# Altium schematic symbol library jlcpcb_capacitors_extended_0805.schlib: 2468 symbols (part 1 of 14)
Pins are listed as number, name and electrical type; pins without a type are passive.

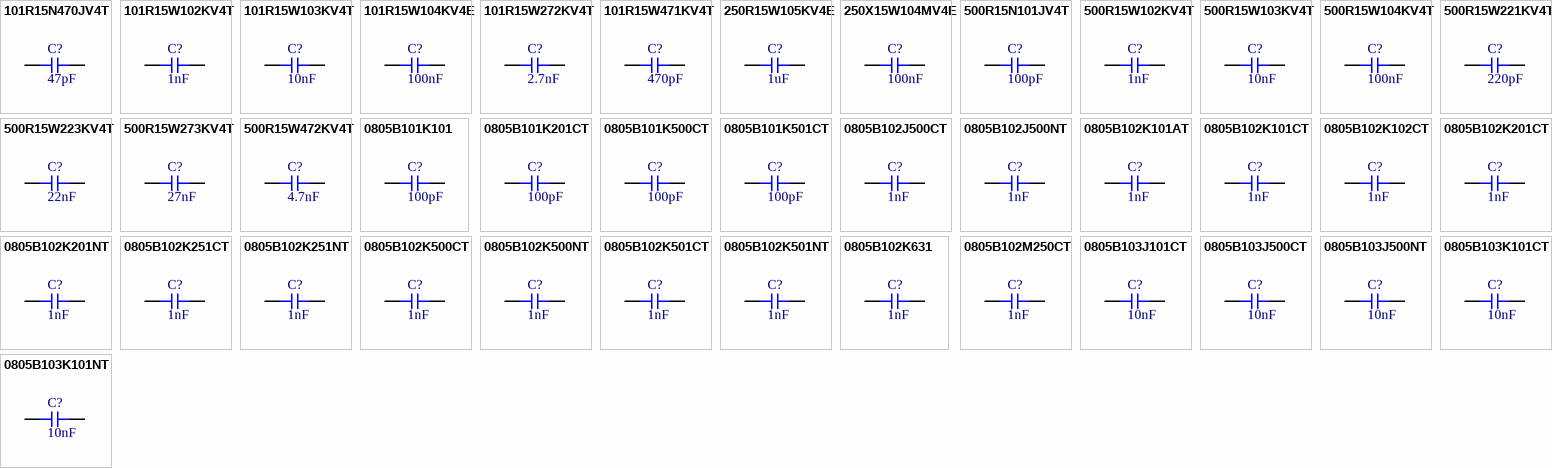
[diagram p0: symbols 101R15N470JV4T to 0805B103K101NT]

## 101R15N470JV4T
designator C?  Capacitance: 47pF  (hidden comment: *)
Capacitor, Ceramic (MLCC), 47pF, ±5%, 100V, NP0, ±5%, SMD 0805; Manufacturer: Johanson Dielectrics; Manufacturer Part Number: 101R15N470JV4T
footprint CAP-0805 (0805 (2012M) Capacitor)
pins: 1, 2

## 101R15W102KV4T
designator C?  Capacitance: 1nF  (hidden comment: *)
Capacitor, Ceramic (MLCC), 1nF, ±10%, 100V, X7R, ±10%, SMD 0805; Manufacturer: Johanson Dielectrics; Manufacturer Part Number: 101R15W102KV4T
footprint CAP-0805 (0805 (2012M) Capacitor)
pins: 1, 2

## 101R15W103KV4T
designator C?  Capacitance: 10nF  (hidden comment: *)
Capacitor, Ceramic (MLCC), 10nF, ±10%, 100V, X7R, ±10%, SMD 0805; Manufacturer: Johanson Dielectrics; Manufacturer Part Number: 101R15W103KV4T
footprint CAP-0805 (0805 (2012M) Capacitor)
pins: 1, 2

## 101R15W104KV4E
designator C?  Capacitance: 100nF  (hidden comment: *)
Capacitor, Ceramic (MLCC), 100nF, ±10%, 100V, X7R, ±10%, SMD 0805; Manufacturer: Johanson Dielectrics; Manufacturer Part Number: 101R15W104KV4E
footprint CAP-0805 (0805 (2012M) Capacitor)
pins: 1, 2

## 101R15W272KV4T
designator C?  Capacitance: 2.7nF  (hidden comment: *)
Capacitor, Ceramic (MLCC), 2.7nF, ±10%, 100V, X7R, ±10%, SMD 0805; Manufacturer: Johanson Dielectrics; Manufacturer Part Number: 101R15W272KV4T
footprint CAP-0805 (0805 (2012M) Capacitor)
pins: 1, 2

## 101R15W471KV4T
designator C?  Capacitance: 470pF  (hidden comment: *)
Capacitor, Ceramic (MLCC), 470pF, ±10%, 100V, X7R, ±10%, SMD 0805; Manufacturer: Johanson Dielectrics; Manufacturer Part Number: 101R15W471KV4T
footprint CAP-0805 (0805 (2012M) Capacitor)
pins: 1, 2

## 250R15W105KV4E
designator C?  Capacitance: 1uF  (hidden comment: *)
Capacitor, Ceramic (MLCC), 1uF, ±10%, 25V, X7R, ±10%, SMD 0805; Manufacturer: Johanson Dielectrics; Manufacturer Part Number: 250R15W105KV4E
footprint CAP-0805 (0805 (2012M) Capacitor)
pins: 1, 2

## 250X15W104MV4E
designator C?  Capacitance: 100nF  (hidden comment: *)
Capacitor, Ceramic (MLCC), 100nF, ±20%, 25V, X7R, ±20%, SMD 0805; Manufacturer: Johanson Dielectrics; Manufacturer Part Number: 250X15W104MV4E
footprint CAP-0805 (0805 (2012M) Capacitor)
pins: 1, 2

## 500R15N101JV4T
designator C?  Capacitance: 100pF  (hidden comment: *)
Capacitor, Ceramic (MLCC), 100pF, ±5%, 50V, NP0, ±5%, SMD 0805; Manufacturer: Johanson Dielectrics; Manufacturer Part Number: 500R15N101JV4T
footprint CAP-0805 (0805 (2012M) Capacitor)
pins: 1, 2

## 500R15W102KV4T
designator C?  Capacitance: 1nF  (hidden comment: *)
Capacitor, Ceramic (MLCC), 1nF, ±10%, 50V, X7R, ±10%, SMD 0805; Manufacturer: Johanson Dielectrics; Manufacturer Part Number: 500R15W102KV4T
footprint CAP-0805 (0805 (2012M) Capacitor)
pins: 1, 2

## 500R15W103KV4T
designator C?  Capacitance: 10nF  (hidden comment: *)
Capacitor, Ceramic (MLCC), 10nF, ±10%, 50V, X7R, ±10%, SMD 0805; Manufacturer: Johanson Dielectrics; Manufacturer Part Number: 500R15W103KV4T
footprint CAP-0805 (0805 (2012M) Capacitor)
pins: 1, 2

## 500R15W104KV4T
designator C?  Capacitance: 100nF  (hidden comment: *)
Capacitor, Ceramic (MLCC), 100nF, ±10%, 50V, X7R, ±10%, SMD 0805; Manufacturer: Johanson Dielectrics; Manufacturer Part Number: 500R15W104KV4T
footprint CAP-0805 (0805 (2012M) Capacitor)
pins: 1, 2

## 500R15W221KV4T
designator C?  Capacitance: 220pF  (hidden comment: *)
Capacitor, Ceramic (MLCC), 220pF, ±10%, 50V, X7R, ±10%, SMD 0805; Manufacturer: Johanson Dielectrics; Manufacturer Part Number: 500R15W221KV4T
footprint CAP-0805 (0805 (2012M) Capacitor)
pins: 1, 2

## 500R15W223KV4T
designator C?  Capacitance: 22nF  (hidden comment: *)
Capacitor, Ceramic (MLCC), 22nF, ±10%, 50V, X7R, ±10%, SMD 0805; Manufacturer: Johanson Dielectrics; Manufacturer Part Number: 500R15W223KV4T
footprint CAP-0805 (0805 (2012M) Capacitor)
pins: 1, 2

## 500R15W273KV4T
designator C?  Capacitance: 27nF  (hidden comment: *)
Capacitor, Ceramic (MLCC), 27nF, ±10%, 50V, X7R, ±10%, SMD 0805; Manufacturer: Johanson Dielectrics; Manufacturer Part Number: 500R15W273KV4T
footprint CAP-0805 (0805 (2012M) Capacitor)
pins: 1, 2

## 500R15W472KV4T
designator C?  Capacitance: 4.7nF  (hidden comment: *)
Capacitor, Ceramic (MLCC), 4.7nF, ±10%, 50V, X7R, ±10%, SMD 0805; Manufacturer: Johanson Dielectrics; Manufacturer Part Number: 500R15W472KV4T
footprint CAP-0805 (0805 (2012M) Capacitor)
pins: 1, 2

## 0805B101K101
designator C?  Capacitance: 100pF  (hidden comment: *)
Capacitor, Ceramic (MLCC), 100pF, ±10%, 100V, X7R, ±10%, SMD 0805; Manufacturer: Walsin Tech Corp; Manufacturer Part Number: 0805B101K101
footprint CAP-0805 (0805 (2012M) Capacitor)
pins: 1, 2

## 0805B101K201CT
designator C?  Capacitance: 100pF  (hidden comment: *)
Capacitor, Ceramic (MLCC), 100pF, ±10%, 200V, X7R, ±10%, SMD 0805; Manufacturer: Walsin Tech Corp; Manufacturer Part Number: 0805B101K201CT
footprint CAP-0805 (0805 (2012M) Capacitor)
pins: 1, 2

## 0805B101K500CT
designator C?  Capacitance: 100pF  (hidden comment: *)
Capacitor, Ceramic (MLCC), 100pF, ±10%, 50V, X7R, ±10%, SMD 0805; Manufacturer: Walsin Tech Corp; Manufacturer Part Number: 0805B101K500CT
footprint CAP-0805 (0805 (2012M) Capacitor)
pins: 1, 2

## 0805B101K501CT
designator C?  Capacitance: 100pF  (hidden comment: *)
Capacitor, Ceramic (MLCC), 100pF, ±10%, 500V, X7R, ±10%, SMD 0805; Manufacturer: Walsin Tech Corp; Manufacturer Part Number: 0805B101K501CT
footprint CAP-0805 (0805 (2012M) Capacitor)
pins: 1, 2

## 0805B102J500CT
designator C?  Capacitance: 1nF  (hidden comment: *)
Capacitor, Ceramic (MLCC), 1nF, ±5%, 50V, X7R, ±5%, SMD 0805; Manufacturer: Walsin Tech Corp; Manufacturer Part Number: 0805B102J500CT
footprint CAP-0805 (0805 (2012M) Capacitor)
pins: 1, 2

## 0805B102J500NT
designator C?  Capacitance: 1nF  (hidden comment: *)
Capacitor, Ceramic (MLCC), 1nF, ±5%, 50V, X7R, ±5%, SMD 0805; Manufacturer: FH(Guangdong Fenghua Advanced Tech); Manufacturer Part Number: 0805B102J500NT
footprint CAP-0805 (0805 (2012M) Capacitor)
pins: 1, 2

## 0805B102K101AT
designator C?  Capacitance: 1nF  (hidden comment: *)
Capacitor, Ceramic (MLCC), 1nF, ±10%, 100V, X7R, ±10%, SMD 0805; Manufacturer: FH(Guangdong Fenghua Advanced Tech); Manufacturer Part Number: 0805B102K101AT
footprint CAP-0805 (0805 (2012M) Capacitor)
pins: 1, 2

## 0805B102K101CT
designator C?  Capacitance: 1nF  (hidden comment: *)
Capacitor, Ceramic (MLCC), 1nF, ±10%, 100V, X7R, ±10%, SMD 0805; Manufacturer: Walsin Tech Corp; Manufacturer Part Number: 0805B102K101CT
footprint CAP-0805 (0805 (2012M) Capacitor)
pins: 1, 2

## 0805B102K102CT
designator C?  Capacitance: 1nF  (hidden comment: *)
Capacitor, Ceramic (MLCC), 1nF, ±10%, 1kV, X7R, ±10%, SMD 0805; Manufacturer: Walsin Tech Corp; Manufacturer Part Number: 0805B102K102CT
footprint CAP-0805 (0805 (2012M) Capacitor)
pins: 1, 2

## 0805B102K201CT
designator C?  Capacitance: 1nF  (hidden comment: *)
Capacitor, Ceramic (MLCC), 1nF, ±10%, 200V, X7R, ±10%, SMD 0805; Manufacturer: Walsin Tech Corp; Manufacturer Part Number: 0805B102K201CT
footprint CAP-0805 (0805 (2012M) Capacitor)
pins: 1, 2

## 0805B102K201NT
designator C?  Capacitance: 1nF  (hidden comment: *)
Capacitor, Ceramic (MLCC), 1nF, ±10%, 200V, X7R, ±10%, SMD 0805; Manufacturer: FH(Guangdong Fenghua Advanced Tech); Manufacturer Part Number: 0805B102K201NT
footprint CAP-0805 (0805 (2012M) Capacitor)
pins: 1, 2

## 0805B102K251CT
designator C?  Capacitance: 1nF  (hidden comment: *)
Capacitor, Ceramic (MLCC), 1nF, ±10%, 250V, X7R, ±10%, SMD 0805; Manufacturer: Walsin Tech Corp; Manufacturer Part Number: 0805B102K251CT
footprint CAP-0805 (0805 (2012M) Capacitor)
pins: 1, 2

## 0805B102K251NT
designator C?  Capacitance: 1nF  (hidden comment: *)
Capacitor, Ceramic (MLCC), 1nF, ±10%, 250V, X7R, ±10%, SMD 0805; Manufacturer: FH(Guangdong Fenghua Advanced Tech); Manufacturer Part Number: 0805B102K251NT
footprint CAP-0805 (0805 (2012M) Capacitor)
pins: 1, 2

## 0805B102K500CT
designator C?  Capacitance: 1nF  (hidden comment: *)
Capacitor, Ceramic (MLCC), 1nF, ±10%, 50V, X7R, ±10%, SMD 0805; Manufacturer: Walsin Tech Corp; Manufacturer Part Number: 0805B102K500CT
footprint CAP-0805 (0805 (2012M) Capacitor)
pins: 1, 2

## 0805B102K500NT
designator C?  Capacitance: 1nF  (hidden comment: *)
Capacitor, Ceramic (MLCC), 1nF, ±10%, 50V, X7R, ±10%, SMD 0805; Manufacturer: FH(Guangdong Fenghua Advanced Tech); Manufacturer Part Number: 0805B102K500NT
footprint CAP-0805 (0805 (2012M) Capacitor)
pins: 1, 2

## 0805B102K501CT
designator C?  Capacitance: 1nF  (hidden comment: *)
Capacitor, Ceramic (MLCC), 1nF, ±10%, 500V, X7R, ±10%, SMD 0805; Manufacturer: Walsin Tech Corp; Manufacturer Part Number: 0805B102K501CT
footprint CAP-0805 (0805 (2012M) Capacitor)
pins: 1, 2

## 0805B102K501NT
designator C?  Capacitance: 1nF  (hidden comment: *)
Capacitor, Ceramic (MLCC), 1nF, ±10%, 500V, ±10%, SMD 0805; Manufacturer: FH(Guangdong Fenghua Advanced Tech); Manufacturer Part Number: 0805B102K501NT
footprint CAP-0805 (0805 (2012M) Capacitor)
pins: 1, 2

## 0805B102K631
designator C?  Capacitance: 1nF  (hidden comment: *)
Capacitor, Ceramic (MLCC), 1nF, ±10%, 630V, X7R, ±10%, SMD 0805; Manufacturer: Walsin Tech Corp; Manufacturer Part Number: 0805B102K631
footprint CAP-0805 (0805 (2012M) Capacitor)
pins: 1, 2

## 0805B102M250CT
designator C?  Capacitance: 1nF  (hidden comment: *)
Capacitor, Ceramic (MLCC), 1nF, ±20%, 25V, X7R, ±20%, SMD 0805; Manufacturer: Walsin Tech Corp; Manufacturer Part Number: 0805B102M250CT
footprint CAP-0805 (0805 (2012M) Capacitor)
pins: 1, 2

## 0805B103J101CT
designator C?  Capacitance: 10nF  (hidden comment: *)
Capacitor, Ceramic (MLCC), 10nF, ±5%, 100V, X7R, ±5%, SMD 0805; Manufacturer: Walsin Tech Corp; Manufacturer Part Number: 0805B103J101CT
footprint CAP-0805 (0805 (2012M) Capacitor)
pins: 1, 2

## 0805B103J500CT
designator C?  Capacitance: 10nF  (hidden comment: *)
Capacitor, Ceramic (MLCC), 10nF, ±5%, 50V, X7R, ±5%, SMD 0805; Manufacturer: Walsin Tech Corp; Manufacturer Part Number: 0805B103J500CT
footprint CAP-0805 (0805 (2012M) Capacitor)
pins: 1, 2

## 0805B103J500NT
designator C?  Capacitance: 10nF  (hidden comment: *)
Capacitor, Ceramic (MLCC), 10nF, ±5%, 50V, X7R, ±5%, SMD 0805; Manufacturer: FH(Guangdong Fenghua Advanced Tech); Manufacturer Part Number: 0805B103J500NT
footprint CAP-0805 (0805 (2012M) Capacitor)
pins: 1, 2

## 0805B103K101CT
designator C?  Capacitance: 10nF  (hidden comment: *)
Capacitor, Ceramic (MLCC), 10nF, ±10%, 100V, X7R, ±10%, SMD 0805; Manufacturer: Walsin Tech Corp; Manufacturer Part Number: 0805B103K101CT
footprint CAP-0805 (0805 (2012M) Capacitor)
pins: 1, 2

## 0805B103K101NT
designator C?  Capacitance: 10nF  (hidden comment: *)
Capacitor, Ceramic (MLCC), 10nF, ±10%, 100V, X7R, ±10%, SMD 0805; Manufacturer: FH(Guangdong Fenghua Advanced Tech); Manufacturer Part Number: 0805B103K101NT
footprint CAP-0805 (0805 (2012M) Capacitor)
pins: 1, 2

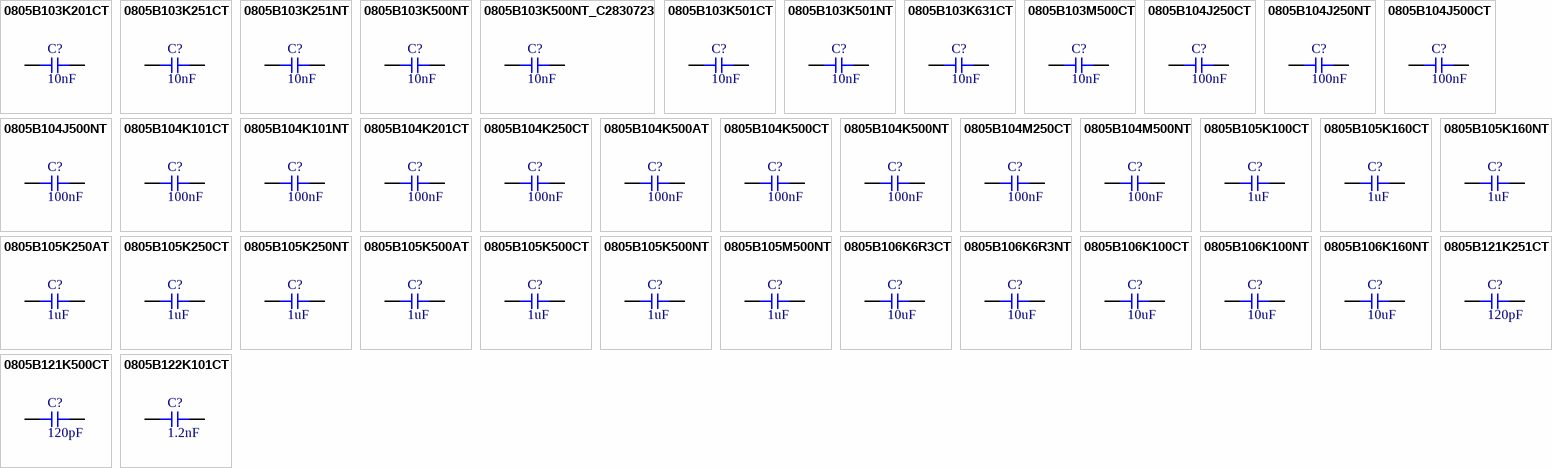
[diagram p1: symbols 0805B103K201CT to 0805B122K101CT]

## 0805B103K201CT
designator C?  Capacitance: 10nF  (hidden comment: *)
Capacitor, Ceramic (MLCC), 10nF, ±10%, 200V, X7R, ±10%, SMD 0805; Manufacturer: Walsin Tech Corp; Manufacturer Part Number: 0805B103K201CT
footprint CAP-0805 (0805 (2012M) Capacitor)
pins: 1, 2

## 0805B103K251CT
designator C?  Capacitance: 10nF  (hidden comment: *)
Capacitor, Ceramic (MLCC), 10nF, ±10%, 250V, X7R, ±10%, SMD 0805; Manufacturer: Walsin Tech Corp; Manufacturer Part Number: 0805B103K251CT
footprint CAP-0805 (0805 (2012M) Capacitor)
pins: 1, 2

## 0805B103K251NT
designator C?  Capacitance: 10nF  (hidden comment: *)
Capacitor, Ceramic (MLCC), 10nF, ±10%, 250V, X7R, ±10%, SMD 0805; Manufacturer: FH(Guangdong Fenghua Advanced Tech); Manufacturer Part Number: 0805B103K251NT
footprint CAP-0805 (0805 (2012M) Capacitor)
pins: 1, 2

## 0805B103K500NT
designator C?  Capacitance: 10nF  (hidden comment: *)
Capacitor, Ceramic (MLCC), 10nF, ±10%, 50V, X7R, ±10%, SMD 0805; Manufacturer: FH(Guangdong Fenghua Advanced Tech); Manufacturer Part Number: 0805B103K500NT
footprint CAP-0805 (0805 (2012M) Capacitor)
pins: 1, 2

## 0805B103K500NT_C2830723
designator C?  Capacitance: 10nF  (hidden comment: *)
Capacitor, Ceramic (MLCC), 10nF, ±10%, 50V, ±10%, SMD 0805; Manufacturer: FH-BK(Guangdong Fenghua Bangke Elec); Manufacturer Part Number: 0805B103K500NT
footprint CAP-0805 (0805 (2012M) Capacitor)
pins: 1, 2

## 0805B103K501CT
designator C?  Capacitance: 10nF  (hidden comment: *)
Capacitor, Ceramic (MLCC), 10nF, ±10%, 500V, X7R, ±10%, SMD 0805; Manufacturer: Walsin Tech Corp; Manufacturer Part Number: 0805B103K501CT
footprint CAP-0805 (0805 (2012M) Capacitor)
pins: 1, 2

## 0805B103K501NT
designator C?  Capacitance: 10nF  (hidden comment: *)
Capacitor, Ceramic (MLCC), 10nF, ±10%, 500V, ±10%, SMD 0805; Manufacturer: FH(Guangdong Fenghua Advanced Tech); Manufacturer Part Number: 0805B103K501NT
footprint CAP-0805 (0805 (2012M) Capacitor)
pins: 1, 2

## 0805B103K631CT
designator C?  Capacitance: 10nF  (hidden comment: *)
Capacitor, Ceramic (MLCC), 10nF, ±10%, 630V, X7R, ±10%, SMD 0805; Manufacturer: Walsin Tech Corp; Manufacturer Part Number: 0805B103K631CT
footprint CAP-0805 (0805 (2012M) Capacitor)
pins: 1, 2

## 0805B103M500CT
designator C?  Capacitance: 10nF  (hidden comment: *)
Capacitor, Ceramic (MLCC), 10nF, ±20%, 50V, X7R, ±20%, SMD 0805; Manufacturer: Walsin Tech Corp; Manufacturer Part Number: 0805B103M500CT
footprint CAP-0805 (0805 (2012M) Capacitor)
pins: 1, 2

## 0805B104J250CT
designator C?  Capacitance: 100nF  (hidden comment: *)
Capacitor, Ceramic (MLCC), 100nF, ±5%, 25V, X7R, ±5%, SMD 0805; Manufacturer: Walsin Tech Corp; Manufacturer Part Number: 0805B104J250CT
footprint CAP-0805 (0805 (2012M) Capacitor)
pins: 1, 2

## 0805B104J250NT
designator C?  Capacitance: 100nF  (hidden comment: *)
Capacitor, Ceramic (MLCC), 100nF, ±5%, 25V, X7R, ±5%, SMD 0805; Manufacturer: FH(Guangdong Fenghua Advanced Tech); Manufacturer Part Number: 0805B104J250NT
footprint CAP-0805 (0805 (2012M) Capacitor)
pins: 1, 2

## 0805B104J500CT
designator C?  Capacitance: 100nF  (hidden comment: *)
Capacitor, Ceramic (MLCC), 100nF, ±5%, 50V, X7R, ±5%, SMD 0805; Manufacturer: Walsin Tech Corp; Manufacturer Part Number: 0805B104J500CT
footprint CAP-0805 (0805 (2012M) Capacitor)
pins: 1, 2

## 0805B104J500NT
designator C?  Capacitance: 100nF  (hidden comment: *)
Capacitor, Ceramic (MLCC), 100nF, ±5%, 50V, X7R, ±5%, SMD 0805; Manufacturer: FH(Guangdong Fenghua Advanced Tech); Manufacturer Part Number: 0805B104J500NT
footprint CAP-0805 (0805 (2012M) Capacitor)
pins: 1, 2

## 0805B104K101CT
designator C?  Capacitance: 100nF  (hidden comment: *)
Capacitor, Ceramic (MLCC), 100nF, ±10%, 100V, X7R, ±10%, SMD 0805; Manufacturer: Walsin Tech Corp; Manufacturer Part Number: 0805B104K101CT
footprint CAP-0805 (0805 (2012M) Capacitor)
pins: 1, 2

## 0805B104K101NT
designator C?  Capacitance: 100nF  (hidden comment: *)
Capacitor, Ceramic (MLCC), 100nF, ±10%, 100V, X7R, ±10%, SMD 0805; Manufacturer: FH(Guangdong Fenghua Advanced Tech); Manufacturer Part Number: 0805B104K101NT
footprint CAP-0805 (0805 (2012M) Capacitor)
pins: 1, 2

## 0805B104K201CT
designator C?  Capacitance: 100nF  (hidden comment: *)
Capacitor, Ceramic (MLCC), 100nF, ±10%, 200V, X7R, ±10%, SMD 0805; Manufacturer: Walsin Tech Corp; Manufacturer Part Number: 0805B104K201CT
footprint CAP-0805 (0805 (2012M) Capacitor)
pins: 1, 2

## 0805B104K250CT
designator C?  Capacitance: 100nF  (hidden comment: *)
Capacitor, Ceramic (MLCC), 100nF, ±10%, 25V, X7R, ±10%, SMD 0805; Manufacturer: Walsin Tech Corp; Manufacturer Part Number: 0805B104K250CT
footprint CAP-0805 (0805 (2012M) Capacitor)
pins: 1, 2

## 0805B104K500AT
designator C?  Capacitance: 100nF  (hidden comment: *)
Capacitor, Ceramic (MLCC), 100nF, ±10%, 50V, ±10%, SMD 0805; Manufacturer: FH(Guangdong Fenghua Advanced Tech); Manufacturer Part Number: 0805B104K500AT
footprint CAP-0805 (0805 (2012M) Capacitor)
pins: 1, 2

## 0805B104K500CT
designator C?  Capacitance: 100nF  (hidden comment: *)
Capacitor, Ceramic (MLCC), 100nF, ±10%, 50V, X7R, ±10%, SMD 0805; Manufacturer: Walsin Tech Corp; Manufacturer Part Number: 0805B104K500CT
footprint CAP-0805 (0805 (2012M) Capacitor)
pins: 1, 2

## 0805B104K500NT
designator C?  Capacitance: 100nF  (hidden comment: *)
Capacitor, Ceramic (MLCC), 100nF, ±10%, 50V, X7R, ±10%, SMD 0805; Manufacturer: FH(Guangdong Fenghua Advanced Tech); Manufacturer Part Number: 0805B104K500NT
footprint CAP-0805 (0805 (2012M) Capacitor)
pins: 1, 2

## 0805B104M250CT
designator C?  Capacitance: 100nF  (hidden comment: *)
Capacitor, Ceramic (MLCC), 100nF, ±20%, 25V, X7R, ±20%, SMD 0805; Manufacturer: Walsin Tech Corp; Manufacturer Part Number: 0805B104M250CT
footprint CAP-0805 (0805 (2012M) Capacitor)
pins: 1, 2

## 0805B104M500NT
designator C?  Capacitance: 100nF  (hidden comment: *)
Capacitor, Ceramic (MLCC), 100nF, ±20%, 50V, X7R, ±20%, SMD 0805; Manufacturer: FH(Guangdong Fenghua Advanced Tech); Manufacturer Part Number: 0805B104M500NT
footprint CAP-0805 (0805 (2012M) Capacitor)
pins: 1, 2

## 0805B105K100CT
designator C?  Capacitance: 1uF  (hidden comment: *)
Capacitor, Ceramic (MLCC), 1uF, ±10%, 10V, X7R, ±10%, SMD 0805; Manufacturer: Walsin Tech Corp; Manufacturer Part Number: 0805B105K100CT
footprint CAP-0805 (0805 (2012M) Capacitor)
pins: 1, 2

## 0805B105K160CT
designator C?  Capacitance: 1uF  (hidden comment: *)
Capacitor, Ceramic (MLCC), 1uF, ±10%, 16V, X7R, ±10%, SMD 0805; Manufacturer: Walsin Tech Corp; Manufacturer Part Number: 0805B105K160CT
footprint CAP-0805 (0805 (2012M) Capacitor)
pins: 1, 2

## 0805B105K160NT
designator C?  Capacitance: 1uF  (hidden comment: *)
Capacitor, Ceramic (MLCC), 1uF, ±10%, 16V, X7R, ±10%, SMD 0805; Manufacturer: FH(Guangdong Fenghua Advanced Tech); Manufacturer Part Number: 0805B105K160NT
footprint CAP-0805 (0805 (2012M) Capacitor)
pins: 1, 2

## 0805B105K250AT
designator C?  Capacitance: 1uF  (hidden comment: *)
Capacitor, Ceramic (MLCC), 1uF, ±10%, 25V, X7R, ±10%, SMD 0805; Manufacturer: FH(Guangdong Fenghua Advanced Tech); Manufacturer Part Number: 0805B105K250AT
footprint CAP-0805 (0805 (2012M) Capacitor)
pins: 1, 2

## 0805B105K250CT
designator C?  Capacitance: 1uF  (hidden comment: *)
Capacitor, Ceramic (MLCC), 1uF, ±10%, 25V, X7R, ±10%, SMD 0805; Manufacturer: Walsin Tech Corp; Manufacturer Part Number: 0805B105K250CT
footprint CAP-0805 (0805 (2012M) Capacitor)
pins: 1, 2

## 0805B105K250NT
designator C?  Capacitance: 1uF  (hidden comment: *)
Capacitor, Ceramic (MLCC), 1uF, ±10%, 25V, X7R, ±10%, SMD 0805; Manufacturer: FH(Guangdong Fenghua Advanced Tech); Manufacturer Part Number: 0805B105K250NT
footprint CAP-0805 (0805 (2012M) Capacitor)
pins: 1, 2

## 0805B105K500AT
designator C?  Capacitance: 1uF  (hidden comment: *)
Capacitor, Ceramic (MLCC), 1uF, ±10%, 50V, X7R, ±10%, SMD 0805; Manufacturer: FH(Guangdong Fenghua Advanced Tech); Manufacturer Part Number: 0805B105K500AT
footprint CAP-0805 (0805 (2012M) Capacitor)
pins: 1, 2

## 0805B105K500CT
designator C?  Capacitance: 1uF  (hidden comment: *)
Capacitor, Ceramic (MLCC), 1uF, ±10%, 50V, X7R, ±10%, SMD 0805; Manufacturer: Walsin Tech Corp; Manufacturer Part Number: 0805B105K500CT
footprint CAP-0805 (0805 (2012M) Capacitor)
pins: 1, 2

## 0805B105K500NT
designator C?  Capacitance: 1uF  (hidden comment: *)
Capacitor, Ceramic (MLCC), 1uF, ±10%, 50V, X7R, ±10%, SMD 0805; Manufacturer: FH(Guangdong Fenghua Advanced Tech); Manufacturer Part Number: 0805B105K500NT
footprint CAP-0805 (0805 (2012M) Capacitor)
pins: 1, 2

## 0805B105M500NT
designator C?  Capacitance: 1uF  (hidden comment: *)
Capacitor, Ceramic (MLCC), 1uF, ±20%, 50V, X7R, ±20%, SMD 0805; Manufacturer: FH (Guangdong Fenghua Advanced Tech); Manufacturer Part Number: 0805B105M500NT
footprint CAP-0805 (0805 (2012M) Capacitor)
pins: 1, 2

## 0805B106K6R3CT
designator C?  Capacitance: 10uF  (hidden comment: *)
Capacitor, Ceramic (MLCC), 10uF, ±10%, 6.3V, X7R, ±10%, SMD 0805; Manufacturer: Walsin Tech Corp; Manufacturer Part Number: 0805B106K6R3CT
footprint CAP-0805 (0805 (2012M) Capacitor)
pins: 1, 2

## 0805B106K6R3NT
designator C?  Capacitance: 10uF  (hidden comment: *)
Capacitor, Ceramic (MLCC), 10uF, ±10%, 6.3V, X7R, ±10%, SMD 0805; Manufacturer: FH(Guangdong Fenghua Advanced Tech); Manufacturer Part Number: 0805B106K6R3NT
footprint CAP-0805 (0805 (2012M) Capacitor)
pins: 1, 2

## 0805B106K100CT
designator C?  Capacitance: 10uF  (hidden comment: *)
Capacitor, Ceramic (MLCC), 10uF, ±10%, 10V, X7R, ±10%, SMD 0805; Manufacturer: Walsin Tech Corp; Manufacturer Part Number: 0805B106K100CT
footprint CAP-0805 (0805 (2012M) Capacitor)
pins: 1, 2

## 0805B106K100NT
designator C?  Capacitance: 10uF  (hidden comment: *)
Capacitor, Ceramic (MLCC), 10uF, ±10%, 10V, X7R, ±10%, SMD 0805; Manufacturer: FH(Guangdong Fenghua Advanced Tech); Manufacturer Part Number: 0805B106K100NT
footprint CAP-0805 (0805 (2012M) Capacitor)
pins: 1, 2

## 0805B106K160NT
designator C?  Capacitance: 10uF  (hidden comment: *)
Capacitor, Ceramic (MLCC), 10uF, ±10%, 16V, X7R, ±10%, SMD 0805; Manufacturer: FH(Guangdong Fenghua Advanced Tech); Manufacturer Part Number: 0805B106K160NT
footprint CAP-0805 (0805 (2012M) Capacitor)
pins: 1, 2

## 0805B121K251CT
designator C?  Capacitance: 120pF  (hidden comment: *)
Capacitor, Ceramic (MLCC), 120pF, ±10%, 250V, X7R, ±10%, SMD 0805; Manufacturer: Walsin Tech Corp; Manufacturer Part Number: 0805B121K251CT
footprint CAP-0805 (0805 (2012M) Capacitor)
pins: 1, 2

## 0805B121K500CT
designator C?  Capacitance: 120pF  (hidden comment: *)
Capacitor, Ceramic (MLCC), 120pF, ±10%, 50V, X7R, ±10%, SMD 0805; Manufacturer: Walsin Tech Corp; Manufacturer Part Number: 0805B121K500CT
footprint CAP-0805 (0805 (2012M) Capacitor)
pins: 1, 2

## 0805B122K101CT
designator C?  Capacitance: 1.2nF  (hidden comment: *)
Capacitor, Ceramic (MLCC), 1.2nF, ±10%, 100V, X7R, ±10%, SMD 0805; Manufacturer: Walsin Tech Corp; Manufacturer Part Number: 0805B122K101CT
footprint CAP-0805 (0805 (2012M) Capacitor)
pins: 1, 2

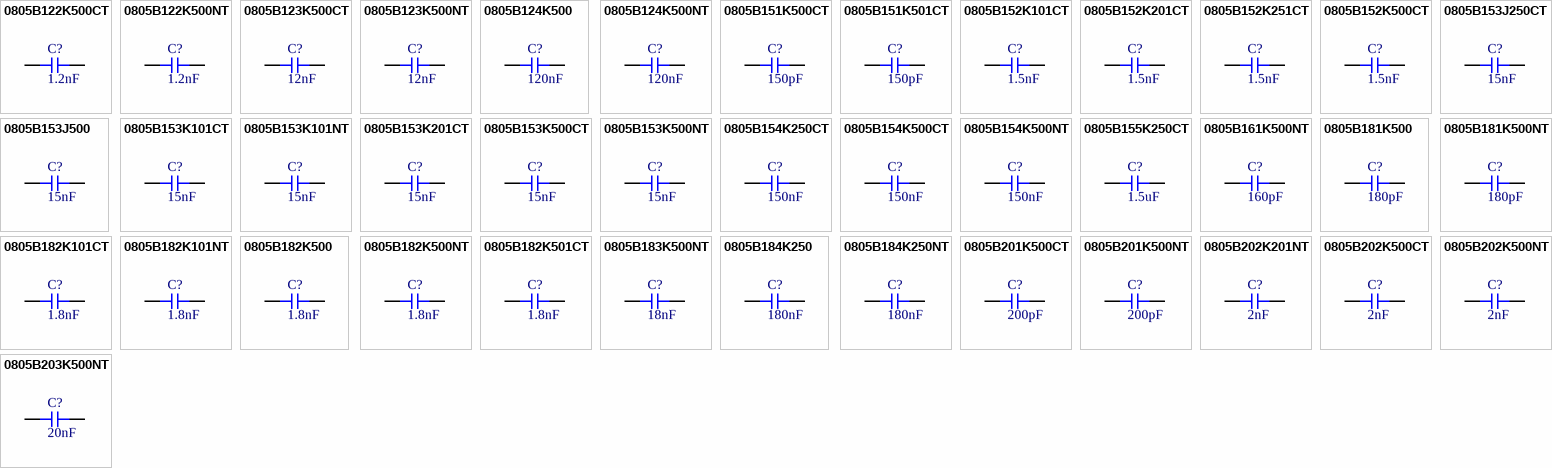
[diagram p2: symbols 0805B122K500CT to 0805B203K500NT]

## 0805B122K500CT
designator C?  Capacitance: 1.2nF  (hidden comment: *)
Capacitor, Ceramic (MLCC), 1.2nF, ±10%, 50V, X7R, ±10%, SMD 0805; Manufacturer: Walsin Tech Corp; Manufacturer Part Number: 0805B122K500CT
footprint CAP-0805 (0805 (2012M) Capacitor)
pins: 1, 2

## 0805B122K500NT
designator C?  Capacitance: 1.2nF  (hidden comment: *)
Capacitor, Ceramic (MLCC), 1.2nF, ±10%, 50V, X7R, ±10%, SMD 0805; Manufacturer: FH(Guangdong Fenghua Advanced Tech); Manufacturer Part Number: 0805B122K500NT
footprint CAP-0805 (0805 (2012M) Capacitor)
pins: 1, 2

## 0805B123K500CT
designator C?  Capacitance: 12nF  (hidden comment: *)
Capacitor, Ceramic (MLCC), 12nF, ±10%, 50V, X7R, ±10%, SMD 0805; Manufacturer: Walsin Tech Corp; Manufacturer Part Number: 0805B123K500CT
footprint CAP-0805 (0805 (2012M) Capacitor)
pins: 1, 2

## 0805B123K500NT
designator C?  Capacitance: 12nF  (hidden comment: *)
Capacitor, Ceramic (MLCC), 12nF, ±10%, 50V, X7R, ±10%, SMD 0805; Manufacturer: FH(Guangdong Fenghua Advanced Tech); Manufacturer Part Number: 0805B123K500NT
footprint CAP-0805 (0805 (2012M) Capacitor)
pins: 1, 2

## 0805B124K500
designator C?  Capacitance: 120nF  (hidden comment: *)
Capacitor, Ceramic (MLCC), 120nF, ±10%, 50V, X7R, ±10%, SMD 0805; Manufacturer: Walsin Tech Corp; Manufacturer Part Number: 0805B124K500
footprint CAP-0805 (0805 (2012M) Capacitor)
pins: 1, 2

## 0805B124K500NT
designator C?  Capacitance: 120nF  (hidden comment: *)
Capacitor, Ceramic (MLCC), 120nF, ±10%, 50V, X7R, ±10%, SMD 0805; Manufacturer: FH(Guangdong Fenghua Advanced Tech); Manufacturer Part Number: 0805B124K500NT
footprint CAP-0805 (0805 (2012M) Capacitor)
pins: 1, 2

## 0805B151K500CT
designator C?  Capacitance: 150pF  (hidden comment: *)
Capacitor, Ceramic (MLCC), 150pF, ±10%, 50V, X7R, ±10%, SMD 0805; Manufacturer: Walsin Tech Corp; Manufacturer Part Number: 0805B151K500CT
footprint CAP-0805 (0805 (2012M) Capacitor)
pins: 1, 2

## 0805B151K501CT
designator C?  Capacitance: 150pF  (hidden comment: *)
Capacitor, Ceramic (MLCC), 150pF, ±10%, 500V, X7R, ±10%, SMD 0805; Manufacturer: Walsin Tech Corp; Manufacturer Part Number: 0805B151K501CT
footprint CAP-0805 (0805 (2012M) Capacitor)
pins: 1, 2

## 0805B152K101CT
designator C?  Capacitance: 1.5nF  (hidden comment: *)
Capacitor, Ceramic (MLCC), 1.5nF, ±10%, 100V, X7R, ±10%, SMD 0805; Manufacturer: Walsin Tech Corp; Manufacturer Part Number: 0805B152K101CT
footprint CAP-0805 (0805 (2012M) Capacitor)
pins: 1, 2

## 0805B152K201CT
designator C?  Capacitance: 1.5nF  (hidden comment: *)
Capacitor, Ceramic (MLCC), 1.5nF, ±10%, 200V, X7R, ±10%, SMD 0805; Manufacturer: Walsin Tech Corp; Manufacturer Part Number: 0805B152K201CT
footprint CAP-0805 (0805 (2012M) Capacitor)
pins: 1, 2

## 0805B152K251CT
designator C?  Capacitance: 1.5nF  (hidden comment: *)
Capacitor, Ceramic (MLCC), 1.5nF, ±10%, 250V, X7R, ±10%, SMD 0805; Manufacturer: Walsin Tech Corp; Manufacturer Part Number: 0805B152K251CT
footprint CAP-0805 (0805 (2012M) Capacitor)
pins: 1, 2

## 0805B152K500CT
designator C?  Capacitance: 1.5nF  (hidden comment: *)
Capacitor, Ceramic (MLCC), 1.5nF, ±10%, 50V, X7R, ±10%, SMD 0805; Manufacturer: Walsin Tech Corp; Manufacturer Part Number: 0805B152K500CT
footprint CAP-0805 (0805 (2012M) Capacitor)
pins: 1, 2

## 0805B153J250CT
designator C?  Capacitance: 15nF  (hidden comment: *)
Capacitor, Ceramic (MLCC), 15nF, ±5%, 25V, X7R, ±5%, SMD 0805; Manufacturer: Walsin Tech Corp; Manufacturer Part Number: 0805B153J250CT
footprint CAP-0805 (0805 (2012M) Capacitor)
pins: 1, 2

## 0805B153J500
designator C?  Capacitance: 15nF  (hidden comment: *)
Capacitor, Ceramic (MLCC), 15nF, ±5%, 50V, X7R, ±5%, SMD 0805; Manufacturer: Walsin Tech Corp; Manufacturer Part Number: 0805B153J500
footprint CAP-0805 (0805 (2012M) Capacitor)
pins: 1, 2

## 0805B153K101CT
designator C?  Capacitance: 15nF  (hidden comment: *)
Capacitor, Ceramic (MLCC), 15nF, ±10%, 100V, X7R, ±10%, SMD 0805; Manufacturer: Walsin Tech Corp; Manufacturer Part Number: 0805B153K101CT
footprint CAP-0805 (0805 (2012M) Capacitor)
pins: 1, 2

## 0805B153K101NT
designator C?  Capacitance: 15nF  (hidden comment: *)
Capacitor, Ceramic (MLCC), 15nF, ±10%, 100V, X7R, ±10%, SMD 0805; Manufacturer: FH(Guangdong Fenghua Advanced Tech); Manufacturer Part Number: 0805B153K101NT
footprint CAP-0805 (0805 (2012M) Capacitor)
pins: 1, 2

## 0805B153K201CT
designator C?  Capacitance: 15nF  (hidden comment: *)
Capacitor, Ceramic (MLCC), 15nF, ±10%, 200V, X7R, ±10%, SMD 0805; Manufacturer: Walsin Tech Corp; Manufacturer Part Number: 0805B153K201CT
footprint CAP-0805 (0805 (2012M) Capacitor)
pins: 1, 2

## 0805B153K500CT
designator C?  Capacitance: 15nF  (hidden comment: *)
Capacitor, Ceramic (MLCC), 15nF, ±10%, 50V, X7R, ±10%, SMD 0805; Manufacturer: Walsin Tech Corp; Manufacturer Part Number: 0805B153K500CT
footprint CAP-0805 (0805 (2012M) Capacitor)
pins: 1, 2

## 0805B153K500NT
designator C?  Capacitance: 15nF  (hidden comment: *)
Capacitor, Ceramic (MLCC), 15nF, ±10%, 50V, X7R, ±10%, SMD 0805; Manufacturer: FH(Guangdong Fenghua Advanced Tech); Manufacturer Part Number: 0805B153K500NT
footprint CAP-0805 (0805 (2012M) Capacitor)
pins: 1, 2

## 0805B154K250CT
designator C?  Capacitance: 150nF  (hidden comment: *)
Capacitor, Ceramic (MLCC), 150nF, ±10%, 25V, X7R, ±10%, SMD 0805; Manufacturer: Walsin Tech Corp; Manufacturer Part Number: 0805B154K250CT
footprint CAP-0805 (0805 (2012M) Capacitor)
pins: 1, 2

## 0805B154K500CT
designator C?  Capacitance: 150nF  (hidden comment: *)
Capacitor, Ceramic (MLCC), 150nF, ±10%, 50V, X7R, ±10%, SMD 0805; Manufacturer: Walsin Tech Corp; Manufacturer Part Number: 0805B154K500CT
footprint CAP-0805 (0805 (2012M) Capacitor)
pins: 1, 2

## 0805B154K500NT
designator C?  Capacitance: 150nF  (hidden comment: *)
Capacitor, Ceramic (MLCC), 150nF, ±10%, 50V, X7R, ±10%, SMD 0805; Manufacturer: FH(Guangdong Fenghua Advanced Tech); Manufacturer Part Number: 0805B154K500NT
footprint CAP-0805 (0805 (2012M) Capacitor)
pins: 1, 2

## 0805B155K250CT
designator C?  Capacitance: 1.5uF  (hidden comment: *)
Capacitor, Ceramic (MLCC), 1.5uF, ±10%, 25V, X7R, ±10%, SMD 0805; Manufacturer: Walsin Tech Corp; Manufacturer Part Number: 0805B155K250CT
footprint CAP-0805 (0805 (2012M) Capacitor)
pins: 1, 2

## 0805B161K500NT
designator C?  Capacitance: 160pF  (hidden comment: *)
Capacitor, Ceramic (MLCC), 160pF, ±10%, 50V, X7R, ±10%, SMD 0805; Manufacturer: FH(Guangdong Fenghua Advanced Tech); Manufacturer Part Number: 0805B161K500NT
footprint CAP-0805 (0805 (2012M) Capacitor)
pins: 1, 2

## 0805B181K500
designator C?  Capacitance: 180pF  (hidden comment: *)
Capacitor, Ceramic (MLCC), 180pF, ±10%, 50V, X7R, ±10%, SMD 0805; Manufacturer: Walsin Tech Corp; Manufacturer Part Number: 0805B181K500
footprint CAP-0805 (0805 (2012M) Capacitor)
pins: 1, 2

## 0805B181K500NT
designator C?  Capacitance: 180pF  (hidden comment: *)
Capacitor, Ceramic (MLCC), 180pF, ±10%, 50V, X7R, ±10%, SMD 0805; Manufacturer: FH(Guangdong Fenghua Advanced Tech); Manufacturer Part Number: 0805B181K500NT
footprint CAP-0805 (0805 (2012M) Capacitor)
pins: 1, 2

## 0805B182K101CT
designator C?  Capacitance: 1.8nF  (hidden comment: *)
Capacitor, Ceramic (MLCC), 1.8nF, ±10%, 100V, X7R, ±10%, SMD 0805; Manufacturer: Walsin Tech Corp; Manufacturer Part Number: 0805B182K101CT
footprint CAP-0805 (0805 (2012M) Capacitor)
pins: 1, 2

## 0805B182K101NT
designator C?  Capacitance: 1.8nF  (hidden comment: *)
Capacitor, Ceramic (MLCC), 1.8nF, ±10%, 100V, X7R, ±10%, SMD 0805; Manufacturer: FH(Guangdong Fenghua Advanced Tech); Manufacturer Part Number: 0805B182K101NT
footprint CAP-0805 (0805 (2012M) Capacitor)
pins: 1, 2

## 0805B182K500
designator C?  Capacitance: 1.8nF  (hidden comment: *)
Capacitor, Ceramic (MLCC), 1.8nF, ±10%, 50V, X7R, ±10%, SMD 0805; Manufacturer: Walsin Tech Corp; Manufacturer Part Number: 0805B182K500
footprint CAP-0805 (0805 (2012M) Capacitor)
pins: 1, 2

## 0805B182K500NT
designator C?  Capacitance: 1.8nF  (hidden comment: *)
Capacitor, Ceramic (MLCC), 1.8nF, ±10%, 50V, X7R, ±10%, SMD 0805; Manufacturer: FH(Guangdong Fenghua Advanced Tech); Manufacturer Part Number: 0805B182K500NT
footprint CAP-0805 (0805 (2012M) Capacitor)
pins: 1, 2

## 0805B182K501CT
designator C?  Capacitance: 1.8nF  (hidden comment: *)
Capacitor, Ceramic (MLCC), 1.8nF, ±10%, 500V, X7R, ±10%, SMD 0805; Manufacturer: Walsin Tech Corp; Manufacturer Part Number: 0805B182K501CT
footprint CAP-0805 (0805 (2012M) Capacitor)
pins: 1, 2

## 0805B183K500NT
designator C?  Capacitance: 18nF  (hidden comment: *)
Capacitor, Ceramic (MLCC), 18nF, ±10%, 50V, X7R, ±10%, SMD 0805; Manufacturer: FH(Guangdong Fenghua Advanced Tech); Manufacturer Part Number: 0805B183K500NT
footprint CAP-0805 (0805 (2012M) Capacitor)
pins: 1, 2

## 0805B184K250
designator C?  Capacitance: 180nF  (hidden comment: *)
Capacitor, Ceramic (MLCC), 180nF, ±10%, 25V, X7R, ±10%, SMD 0805; Manufacturer: Walsin Tech Corp; Manufacturer Part Number: 0805B184K250
footprint CAP-0805 (0805 (2012M) Capacitor)
pins: 1, 2

## 0805B184K250NT
designator C?  Capacitance: 180nF  (hidden comment: *)
Capacitor, Ceramic (MLCC), 180nF, ±10%, 25V, X7R, ±10%, SMD 0805; Manufacturer: FH(Guangdong Fenghua Advanced Tech); Manufacturer Part Number: 0805B184K250NT
footprint CAP-0805 (0805 (2012M) Capacitor)
pins: 1, 2

## 0805B201K500CT
designator C?  Capacitance: 200pF  (hidden comment: *)
Capacitor, Ceramic (MLCC), 200pF, ±10%, 50V, X7R, ±10%, SMD 0805; Manufacturer: Walsin Tech Corp; Manufacturer Part Number: 0805B201K500CT
footprint CAP-0805 (0805 (2012M) Capacitor)
pins: 1, 2

## 0805B201K500NT
designator C?  Capacitance: 200pF  (hidden comment: *)
Capacitor, Ceramic (MLCC), 200pF, ±10%, 50V, X7R, ±10%, SMD 0805; Manufacturer: FH(Guangdong Fenghua Advanced Tech); Manufacturer Part Number: 0805B201K500NT
footprint CAP-0805 (0805 (2012M) Capacitor)
pins: 1, 2

## 0805B202K201NT
designator C?  Capacitance: 2nF  (hidden comment: *)
Capacitor, Ceramic (MLCC), 2nF, ±10%, 200V, X7R, ±10%, SMD 0805; Manufacturer: FH(Guangdong Fenghua Advanced Tech); Manufacturer Part Number: 0805B202K201NT
footprint CAP-0805 (0805 (2012M) Capacitor)
pins: 1, 2

## 0805B202K500CT
designator C?  Capacitance: 2nF  (hidden comment: *)
Capacitor, Ceramic (MLCC), 2nF, ±10%, 50V, X7R, ±10%, SMD 0805; Manufacturer: Walsin Tech Corp; Manufacturer Part Number: 0805B202K500CT
footprint CAP-0805 (0805 (2012M) Capacitor)
pins: 1, 2

## 0805B202K500NT
designator C?  Capacitance: 2nF  (hidden comment: *)
Capacitor, Ceramic (MLCC), 2nF, ±10%, 50V, X7R, ±10%, SMD 0805; Manufacturer: FH(Guangdong Fenghua Advanced Tech); Manufacturer Part Number: 0805B202K500NT
footprint CAP-0805 (0805 (2012M) Capacitor)
pins: 1, 2

## 0805B203K500NT
designator C?  Capacitance: 20nF  (hidden comment: *)
Capacitor, Ceramic (MLCC), 20nF, ±10%, 50V, X7R, ±10%, SMD 0805; Manufacturer: FH(Guangdong Fenghua Advanced Tech); Manufacturer Part Number: 0805B203K500NT
footprint CAP-0805 (0805 (2012M) Capacitor)
pins: 1, 2

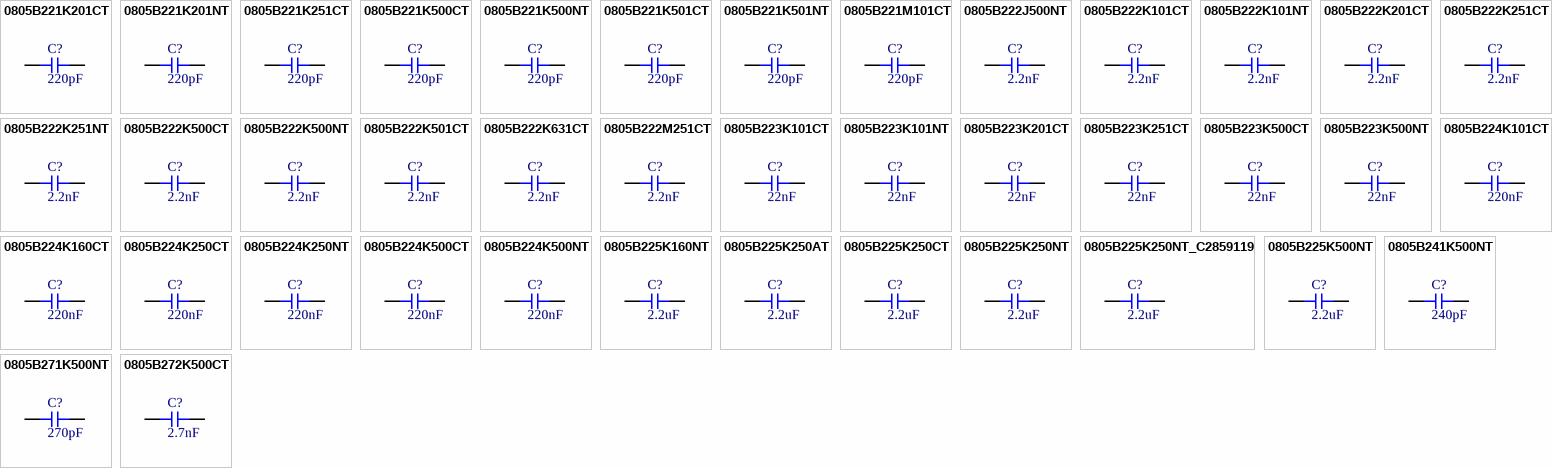
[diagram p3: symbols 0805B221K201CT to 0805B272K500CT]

## 0805B221K201CT
designator C?  Capacitance: 220pF  (hidden comment: *)
Capacitor, Ceramic (MLCC), 220pF, ±10%, 200V, X7R, ±10%, SMD 0805; Manufacturer: Walsin Tech Corp; Manufacturer Part Number: 0805B221K201CT
footprint CAP-0805 (0805 (2012M) Capacitor)
pins: 1, 2

## 0805B221K201NT
designator C?  Capacitance: 220pF  (hidden comment: *)
Capacitor, Ceramic (MLCC), 220pF, ±10%, 200V, X7R, ±10%, SMD 0805; Manufacturer: FH(Guangdong Fenghua Advanced Tech); Manufacturer Part Number: 0805B221K201NT
footprint CAP-0805 (0805 (2012M) Capacitor)
pins: 1, 2

## 0805B221K251CT
designator C?  Capacitance: 220pF  (hidden comment: *)
Capacitor, Ceramic (MLCC), 220pF, ±10%, 250V, X7R, ±10%, SMD 0805; Manufacturer: Walsin Tech Corp; Manufacturer Part Number: 0805B221K251CT
footprint CAP-0805 (0805 (2012M) Capacitor)
pins: 1, 2

## 0805B221K500CT
designator C?  Capacitance: 220pF  (hidden comment: *)
Capacitor, Ceramic (MLCC), 220pF, ±10%, 50V, X7R, ±10%, SMD 0805; Manufacturer: Walsin Tech Corp; Manufacturer Part Number: 0805B221K500CT
footprint CAP-0805 (0805 (2012M) Capacitor)
pins: 1, 2

## 0805B221K500NT
designator C?  Capacitance: 220pF  (hidden comment: *)
Capacitor, Ceramic (MLCC), 220pF, ±10%, 50V, X7R, ±10%, SMD 0805; Manufacturer: FH(Guangdong Fenghua Advanced Tech); Manufacturer Part Number: 0805B221K500NT
footprint CAP-0805 (0805 (2012M) Capacitor)
pins: 1, 2

## 0805B221K501CT
designator C?  Capacitance: 220pF  (hidden comment: *)
Capacitor, Ceramic (MLCC), 220pF, ±10%, 500V, X7R, ±10%, SMD 0805; Manufacturer: Walsin Tech Corp; Manufacturer Part Number: 0805B221K501CT
footprint CAP-0805 (0805 (2012M) Capacitor)
pins: 1, 2

## 0805B221K501NT
designator C?  Capacitance: 220pF  (hidden comment: *)
Capacitor, Ceramic (MLCC), 220pF, ±10%, 500V, X7R, ±10%, SMD 0805; Manufacturer: FH(Guangdong Fenghua Advanced Tech); Manufacturer Part Number: 0805B221K501NT
footprint CAP-0805 (0805 (2012M) Capacitor)
pins: 1, 2

## 0805B221M101CT
designator C?  Capacitance: 220pF  (hidden comment: *)
Capacitor, Ceramic (MLCC), 220pF, ±20%, 100V, X7R, ±20%, SMD 0805; Manufacturer: Walsin Tech Corp; Manufacturer Part Number: 0805B221M101CT
footprint CAP-0805 (0805 (2012M) Capacitor)
pins: 1, 2

## 0805B222J500NT
designator C?  Capacitance: 2.2nF  (hidden comment: *)
Capacitor, Ceramic (MLCC), 2.2nF, ±5%, 50V, ±5%, SMD 0805; Manufacturer: FH(Guangdong Fenghua Advanced Tech); Manufacturer Part Number: 0805B222J500NT
footprint CAP-0805 (0805 (2012M) Capacitor)
pins: 1, 2

## 0805B222K101CT
designator C?  Capacitance: 2.2nF  (hidden comment: *)
Capacitor, Ceramic (MLCC), 2.2nF, ±10%, 100V, X7R, ±10%, SMD 0805; Manufacturer: Walsin Tech Corp; Manufacturer Part Number: 0805B222K101CT
footprint CAP-0805 (0805 (2012M) Capacitor)
pins: 1, 2

## 0805B222K101NT
designator C?  Capacitance: 2.2nF  (hidden comment: *)
Capacitor, Ceramic (MLCC), 2.2nF, ±10%, 100V, X7R, ±10%, SMD 0805; Manufacturer: FH(Guangdong Fenghua Advanced Tech); Manufacturer Part Number: 0805B222K101NT
footprint CAP-0805 (0805 (2012M) Capacitor)
pins: 1, 2

## 0805B222K201CT
designator C?  Capacitance: 2.2nF  (hidden comment: *)
Capacitor, Ceramic (MLCC), 2.2nF, ±10%, 200V, X7R, ±10%, SMD 0805; Manufacturer: Walsin Tech Corp; Manufacturer Part Number: 0805B222K201CT
footprint CAP-0805 (0805 (2012M) Capacitor)
pins: 1, 2

## 0805B222K251CT
designator C?  Capacitance: 2.2nF  (hidden comment: *)
Capacitor, Ceramic (MLCC), 2.2nF, ±10%, 250V, X7R, ±10%, SMD 0805; Manufacturer: Walsin Tech Corp; Manufacturer Part Number: 0805B222K251CT
footprint CAP-0805 (0805 (2012M) Capacitor)
pins: 1, 2

## 0805B222K251NT
designator C?  Capacitance: 2.2nF  (hidden comment: *)
Capacitor, Ceramic (MLCC), 2.2nF, ±10%, 250V, X7R, ±10%, SMD 0805; Manufacturer: FH(Guangdong Fenghua Advanced Tech); Manufacturer Part Number: 0805B222K251NT
footprint CAP-0805 (0805 (2012M) Capacitor)
pins: 1, 2

## 0805B222K500CT
designator C?  Capacitance: 2.2nF  (hidden comment: *)
Capacitor, Ceramic (MLCC), 2.2nF, ±10%, 50V, X7R, ±10%, SMD 0805; Manufacturer: Walsin Tech Corp; Manufacturer Part Number: 0805B222K500CT
footprint CAP-0805 (0805 (2012M) Capacitor)
pins: 1, 2

## 0805B222K500NT
designator C?  Capacitance: 2.2nF  (hidden comment: *)
Capacitor, Ceramic (MLCC), 2.2nF, ±10%, 50V, X7R, ±10%, SMD 0805; Manufacturer: FH(Guangdong Fenghua Advanced Tech); Manufacturer Part Number: 0805B222K500NT
footprint CAP-0805 (0805 (2012M) Capacitor)
pins: 1, 2

## 0805B222K501CT
designator C?  Capacitance: 2.2nF  (hidden comment: *)
Capacitor, Ceramic (MLCC), 2.2nF, ±10%, 500V, X7R, ±10%, SMD 0805; Manufacturer: Walsin Tech Corp; Manufacturer Part Number: 0805B222K501CT
footprint CAP-0805 (0805 (2012M) Capacitor)
pins: 1, 2

## 0805B222K631CT
designator C?  Capacitance: 2.2nF  (hidden comment: *)
Capacitor, Ceramic (MLCC), 2.2nF, ±10%, 630V, X7R, ±10%, SMD 0805; Manufacturer: Walsin Tech Corp; Manufacturer Part Number: 0805B222K631CT
footprint CAP-0805 (0805 (2012M) Capacitor)
pins: 1, 2

## 0805B222M251CT
designator C?  Capacitance: 2.2nF  (hidden comment: *)
Capacitor, Ceramic (MLCC), 2.2nF, ±20%, 250V, X7R, ±20%, SMD 0805; Manufacturer: Walsin Tech Corp; Manufacturer Part Number: 0805B222M251CT
footprint CAP-0805 (0805 (2012M) Capacitor)
pins: 1, 2

## 0805B223K101CT
designator C?  Capacitance: 22nF  (hidden comment: *)
Capacitor, Ceramic (MLCC), 22nF, ±10%, 100V, X7R, ±10%, SMD 0805; Manufacturer: Walsin Tech Corp; Manufacturer Part Number: 0805B223K101CT
footprint CAP-0805 (0805 (2012M) Capacitor)
pins: 1, 2

## 0805B223K101NT
designator C?  Capacitance: 22nF  (hidden comment: *)
Capacitor, Ceramic (MLCC), 22nF, ±10%, 100V, X7R, ±10%, SMD 0805; Manufacturer: FH(Guangdong Fenghua Advanced Tech); Manufacturer Part Number: 0805B223K101NT
footprint CAP-0805 (0805 (2012M) Capacitor)
pins: 1, 2

## 0805B223K201CT
designator C?  Capacitance: 22nF  (hidden comment: *)
Capacitor, Ceramic (MLCC), 22nF, ±10%, 200V, X7R, ±10%, SMD 0805; Manufacturer: Walsin Tech Corp; Manufacturer Part Number: 0805B223K201CT
footprint CAP-0805 (0805 (2012M) Capacitor)
pins: 1, 2

## 0805B223K251CT
designator C?  Capacitance: 22nF  (hidden comment: *)
Capacitor, Ceramic (MLCC), 22nF, ±10%, 250V, X7R, ±10%, SMD 0805; Manufacturer: Walsin Tech Corp; Manufacturer Part Number: 0805B223K251CT
footprint CAP-0805 (0805 (2012M) Capacitor)
pins: 1, 2

## 0805B223K500CT
designator C?  Capacitance: 22nF  (hidden comment: *)
Capacitor, Ceramic (MLCC), 22nF, ±10%, 50V, X7R, ±10%, SMD 0805; Manufacturer: Walsin Tech Corp; Manufacturer Part Number: 0805B223K500CT
footprint CAP-0805 (0805 (2012M) Capacitor)
pins: 1, 2

## 0805B223K500NT
designator C?  Capacitance: 22nF  (hidden comment: *)
Capacitor, Ceramic (MLCC), 22nF, ±10%, 50V, X7R, ±10%, SMD 0805; Manufacturer: FH(Guangdong Fenghua Advanced Tech); Manufacturer Part Number: 0805B223K500NT
footprint CAP-0805 (0805 (2012M) Capacitor)
pins: 1, 2

## 0805B224K101CT
designator C?  Capacitance: 220nF  (hidden comment: *)
Capacitor, Ceramic (MLCC), 220nF, ±10%, 100V, X7R, ±10%, SMD 0805; Manufacturer: Walsin Tech Corp; Manufacturer Part Number: 0805B224K101CT
footprint CAP-0805 (0805 (2012M) Capacitor)
pins: 1, 2

## 0805B224K160CT
designator C?  Capacitance: 220nF  (hidden comment: *)
Capacitor, Ceramic (MLCC), 220nF, ±10%, 16V, X7R, ±10%, SMD 0805; Manufacturer: Walsin Tech Corp; Manufacturer Part Number: 0805B224K160CT
footprint CAP-0805 (0805 (2012M) Capacitor)
pins: 1, 2

## 0805B224K250CT
designator C?  Capacitance: 220nF  (hidden comment: *)
Capacitor, Ceramic (MLCC), 220nF, ±10%, 25V, X7R, ±10%, SMD 0805; Manufacturer: Walsin Tech Corp; Manufacturer Part Number: 0805B224K250CT
footprint CAP-0805 (0805 (2012M) Capacitor)
pins: 1, 2

## 0805B224K250NT
designator C?  Capacitance: 220nF  (hidden comment: *)
Capacitor, Ceramic (MLCC), 220nF, ±10%, 25V, X7R, ±10%, SMD 0805; Manufacturer: FH(Guangdong Fenghua Advanced Tech); Manufacturer Part Number: 0805B224K250NT
footprint CAP-0805 (0805 (2012M) Capacitor)
pins: 1, 2

## 0805B224K500CT
designator C?  Capacitance: 220nF  (hidden comment: *)
Capacitor, Ceramic (MLCC), 220nF, ±10%, 50V, X7R, ±10%, SMD 0805; Manufacturer: Walsin Tech Corp; Manufacturer Part Number: 0805B224K500CT
footprint CAP-0805 (0805 (2012M) Capacitor)
pins: 1, 2

## 0805B224K500NT
designator C?  Capacitance: 220nF  (hidden comment: *)
Capacitor, Ceramic (MLCC), 220nF, ±10%, 50V, X7R, ±10%, SMD 0805; Manufacturer: FH(Guangdong Fenghua Advanced Tech); Manufacturer Part Number: 0805B224K500NT
footprint CAP-0805 (0805 (2012M) Capacitor)
pins: 1, 2

## 0805B225K160NT
designator C?  Capacitance: 2.2uF  (hidden comment: *)
Capacitor, Ceramic (MLCC), 2.2uF, ±10%, 16V, X7R, ±10%, SMD 0805; Manufacturer: FH(Guangdong Fenghua Advanced Tech); Manufacturer Part Number: 0805B225K160NT
footprint CAP-0805 (0805 (2012M) Capacitor)
pins: 1, 2

## 0805B225K250AT
designator C?  Capacitance: 2.2uF  (hidden comment: *)
Capacitor, Ceramic (MLCC), 2.2uF, ±10%, 25V, X7R, ±10%, SMD 0805; Manufacturer: FH(Guangdong Fenghua Advanced Tech); Manufacturer Part Number: 0805B225K250AT
footprint CAP-0805 (0805 (2012M) Capacitor)
pins: 1, 2

## 0805B225K250CT
designator C?  Capacitance: 2.2uF  (hidden comment: *)
Capacitor, Ceramic (MLCC), 2.2uF, ±10%, 25V, X7R, ±10%, SMD 0805; Manufacturer: Walsin Tech Corp; Manufacturer Part Number: 0805B225K250CT
footprint CAP-0805 (0805 (2012M) Capacitor)
pins: 1, 2

## 0805B225K250NT
designator C?  Capacitance: 2.2uF  (hidden comment: *)
Capacitor, Ceramic (MLCC), 2.2uF, ±10%, 25V, X7R, ±10%, SMD 0805; Manufacturer: FH(Guangdong Fenghua Advanced Tech); Manufacturer Part Number: 0805B225K250NT
footprint CAP-0805 (0805 (2012M) Capacitor)
pins: 1, 2

## 0805B225K250NT_C2859119
designator C?  Capacitance: 2.2uF  (hidden comment: *)
Capacitor, Ceramic (MLCC), 2.2uF, ±10%, 25V, ±10%, SMD 0805; Manufacturer: FH(Guangdong Fenghua Advanced Tech); Manufacturer Part Number: 0805B225K250NT
footprint CAP-0805 (0805 (2012M) Capacitor)
pins: 1, 2

## 0805B225K500NT
designator C?  Capacitance: 2.2uF  (hidden comment: *)
Capacitor, Ceramic (MLCC), 2.2uF, ±10%, 50V, ±10%, SMD 0805; Manufacturer: FH(Guangdong Fenghua Advanced Tech); Manufacturer Part Number: 0805B225K500NT
footprint CAP-0805 (0805 (2012M) Capacitor)
pins: 1, 2

## 0805B241K500NT
designator C?  Capacitance: 240pF  (hidden comment: *)
Capacitor, Ceramic (MLCC), 240pF, ±10%, 50V, X7R, ±10%, SMD 0805; Manufacturer: FH(Guangdong Fenghua Advanced Tech); Manufacturer Part Number: 0805B241K500NT
footprint CAP-0805 (0805 (2012M) Capacitor)
pins: 1, 2

## 0805B271K500NT
designator C?  Capacitance: 270pF  (hidden comment: *)
Capacitor, Ceramic (MLCC), 270pF, ±10%, 50V, X7R, ±10%, SMD 0805; Manufacturer: FH(Guangdong Fenghua Advanced Tech); Manufacturer Part Number: 0805B271K500NT
footprint CAP-0805 (0805 (2012M) Capacitor)
pins: 1, 2

## 0805B272K500CT
designator C?  Capacitance: 2.7nF  (hidden comment: *)
Capacitor, Ceramic (MLCC), 2.7nF, ±10%, 50V, X7R, ±10%, SMD 0805; Manufacturer: Walsin Tech Corp; Manufacturer Part Number: 0805B272K500CT
footprint CAP-0805 (0805 (2012M) Capacitor)
pins: 1, 2

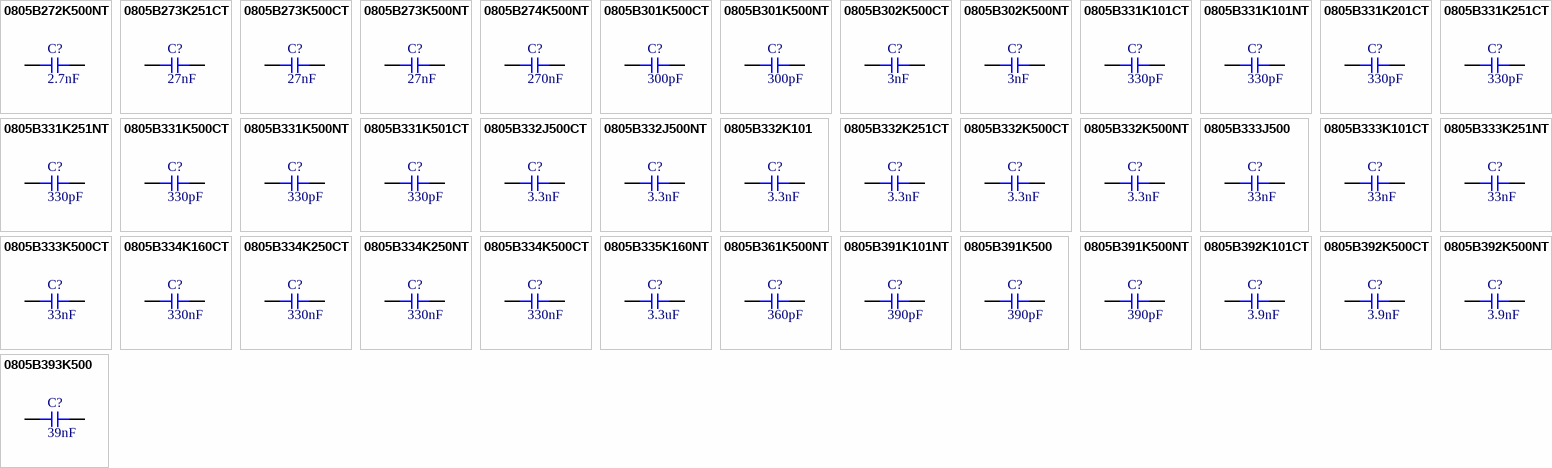
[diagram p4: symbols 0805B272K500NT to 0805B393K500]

## 0805B272K500NT
designator C?  Capacitance: 2.7nF  (hidden comment: *)
Capacitor, Ceramic (MLCC), 2.7nF, ±10%, 50V, X7R, ±10%, SMD 0805; Manufacturer: FH(Guangdong Fenghua Advanced Tech); Manufacturer Part Number: 0805B272K500NT
footprint CAP-0805 (0805 (2012M) Capacitor)
pins: 1, 2

## 0805B273K251CT
designator C?  Capacitance: 27nF  (hidden comment: *)
Capacitor, Ceramic (MLCC), 27nF, ±10%, 250V, X7R, ±10%, SMD 0805; Manufacturer: Walsin Tech Corp; Manufacturer Part Number: 0805B273K251CT
footprint CAP-0805 (0805 (2012M) Capacitor)
pins: 1, 2

## 0805B273K500CT
designator C?  Capacitance: 27nF  (hidden comment: *)
Capacitor, Ceramic (MLCC), 27nF, ±10%, 50V, X7R, ±10%, SMD 0805; Manufacturer: Walsin Tech Corp; Manufacturer Part Number: 0805B273K500CT
footprint CAP-0805 (0805 (2012M) Capacitor)
pins: 1, 2

## 0805B273K500NT
designator C?  Capacitance: 27nF  (hidden comment: *)
Capacitor, Ceramic (MLCC), 27nF, ±10%, 50V, X7R, ±10%, SMD 0805; Manufacturer: FH(Guangdong Fenghua Advanced Tech); Manufacturer Part Number: 0805B273K500NT
footprint CAP-0805 (0805 (2012M) Capacitor)
pins: 1, 2

## 0805B274K500NT
designator C?  Capacitance: 270nF  (hidden comment: *)
Capacitor, Ceramic (MLCC), 270nF, ±10%, 50V, ±10%, SMD 0805; Manufacturer: FH(Guangdong Fenghua Advanced Tech); Manufacturer Part Number: 0805B274K500NT
footprint CAP-0805 (0805 (2012M) Capacitor)
pins: 1, 2

## 0805B301K500CT
designator C?  Capacitance: 300pF  (hidden comment: *)
Capacitor, Ceramic (MLCC), 300pF, ±10%, 50V, X7R, ±10%, SMD 0805; Manufacturer: Walsin Tech Corp; Manufacturer Part Number: 0805B301K500CT
footprint CAP-0805 (0805 (2012M) Capacitor)
pins: 1, 2

## 0805B301K500NT
designator C?  Capacitance: 300pF  (hidden comment: *)
Capacitor, Ceramic (MLCC), 300pF, ±10%, 50V, X7R, ±10%, SMD 0805; Manufacturer: FH(Guangdong Fenghua Advanced Tech); Manufacturer Part Number: 0805B301K500NT
footprint CAP-0805 (0805 (2012M) Capacitor)
pins: 1, 2

## 0805B302K500CT
designator C?  Capacitance: 3nF  (hidden comment: *)
Capacitor, Ceramic (MLCC), 3nF, ±10%, 50V, X7R, ±10%, SMD 0805; Manufacturer: Walsin Tech Corp; Manufacturer Part Number: 0805B302K500CT
footprint CAP-0805 (0805 (2012M) Capacitor)
pins: 1, 2

## 0805B302K500NT
designator C?  Capacitance: 3nF  (hidden comment: *)
Capacitor, Ceramic (MLCC), 3nF, ±10%, 50V, X7R, ±10%, SMD 0805; Manufacturer: FH(Guangdong Fenghua Advanced Tech); Manufacturer Part Number: 0805B302K500NT
footprint CAP-0805 (0805 (2012M) Capacitor)
pins: 1, 2

## 0805B331K101CT
designator C?  Capacitance: 330pF  (hidden comment: *)
Capacitor, Ceramic (MLCC), 330pF, ±10%, 100V, X7R, ±10%, SMD 0805; Manufacturer: Walsin Tech Corp; Manufacturer Part Number: 0805B331K101CT
footprint CAP-0805 (0805 (2012M) Capacitor)
pins: 1, 2

## 0805B331K101NT
designator C?  Capacitance: 330pF  (hidden comment: *)
Capacitor, Ceramic (MLCC), 330pF, ±10%, 100V, X7R, ±10%, SMD 0805; Manufacturer: FH(Guangdong Fenghua Advanced Tech); Manufacturer Part Number: 0805B331K101NT
footprint CAP-0805 (0805 (2012M) Capacitor)
pins: 1, 2

## 0805B331K201CT
designator C?  Capacitance: 330pF  (hidden comment: *)
Capacitor, Ceramic (MLCC), 330pF, ±10%, 200V, X7R, ±10%, SMD 0805; Manufacturer: Walsin Tech Corp; Manufacturer Part Number: 0805B331K201CT
footprint CAP-0805 (0805 (2012M) Capacitor)
pins: 1, 2

## 0805B331K251CT
designator C?  Capacitance: 330pF  (hidden comment: *)
Capacitor, Ceramic (MLCC), 330pF, ±10%, 250V, X7R, ±10%, SMD 0805; Manufacturer: Walsin Tech Corp; Manufacturer Part Number: 0805B331K251CT
footprint CAP-0805 (0805 (2012M) Capacitor)
pins: 1, 2

## 0805B331K251NT
designator C?  Capacitance: 330pF  (hidden comment: *)
Capacitor, Ceramic (MLCC), 330pF, ±10%, 250V, X7R, ±10%, SMD 0805; Manufacturer: FH-BK(Guangdong Fenghua Bangke Elec); Manufacturer Part Number: 0805B331K251NT
footprint CAP-0805 (0805 (2012M) Capacitor)
pins: 1, 2

## 0805B331K500CT
designator C?  Capacitance: 330pF  (hidden comment: *)
Capacitor, Ceramic (MLCC), 330pF, ±10%, 50V, X7R, ±10%, SMD 0805; Manufacturer: Walsin Tech Corp; Manufacturer Part Number: 0805B331K500CT
footprint CAP-0805 (0805 (2012M) Capacitor)
pins: 1, 2

## 0805B331K500NT
designator C?  Capacitance: 330pF  (hidden comment: *)
Capacitor, Ceramic (MLCC), 330pF, ±10%, 50V, X7R, ±10%, SMD 0805; Manufacturer: FH(Guangdong Fenghua Advanced Tech); Manufacturer Part Number: 0805B331K500NT
footprint CAP-0805 (0805 (2012M) Capacitor)
pins: 1, 2

## 0805B331K501CT
designator C?  Capacitance: 330pF  (hidden comment: *)
Capacitor, Ceramic (MLCC), 330pF, ±10%, 500V, X7R, ±10%, SMD 0805; Manufacturer: Walsin Tech Corp; Manufacturer Part Number: 0805B331K501CT
footprint CAP-0805 (0805 (2012M) Capacitor)
pins: 1, 2

## 0805B332J500CT
designator C?  Capacitance: 3.3nF  (hidden comment: *)
Capacitor, Ceramic (MLCC), 3.3nF, ±5%, 50V, X7R, ±5%, SMD 0805; Manufacturer: Walsin Tech Corp; Manufacturer Part Number: 0805B332J500CT
footprint CAP-0805 (0805 (2012M) Capacitor)
pins: 1, 2

## 0805B332J500NT
designator C?  Capacitance: 3.3nF  (hidden comment: *)
Capacitor, Ceramic (MLCC), 3.3nF, ±5%, 50V, ±5%, SMD 0805; Manufacturer: FH(Guangdong Fenghua Advanced Tech); Manufacturer Part Number: 0805B332J500NT
footprint CAP-0805 (0805 (2012M) Capacitor)
pins: 1, 2

## 0805B332K101
designator C?  Capacitance: 3.3nF  (hidden comment: *)
Capacitor, Ceramic (MLCC), 3.3nF, ±10%, 100V, X7R, ±10%, SMD 0805; Manufacturer: Walsin Tech Corp; Manufacturer Part Number: 0805B332K101
footprint CAP-0805 (0805 (2012M) Capacitor)
pins: 1, 2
